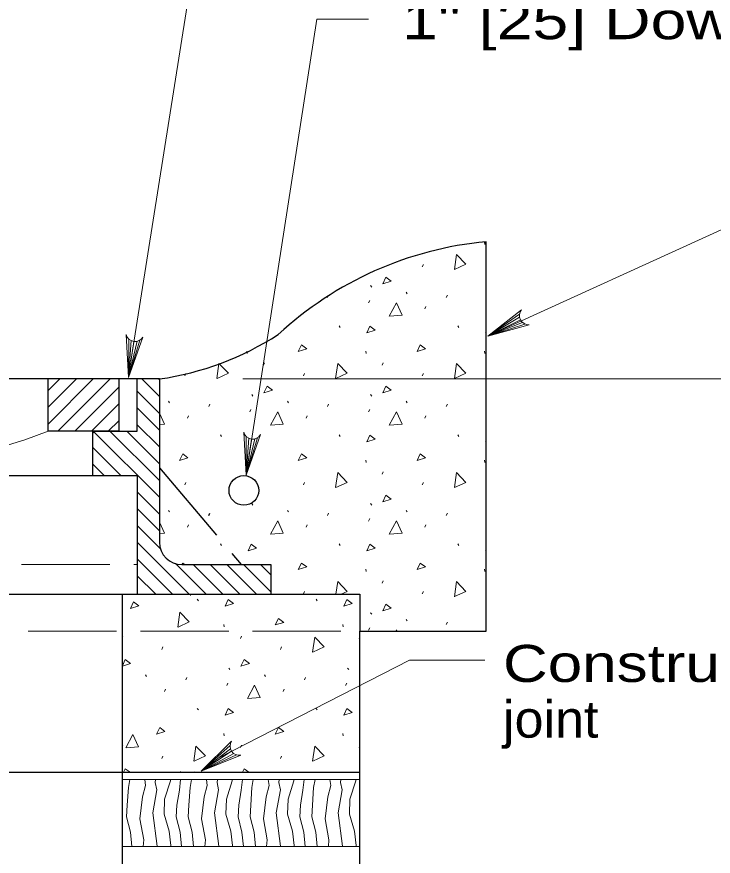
# Model space of a CAD drawing. Extents: x 1083.1 to 1117.1, y 719.4 to 763.4.
# Drawn here: x 1108.838 to 1111.769, y 732.781 to 736.318 of the extents above; entities that cross this region are included whole.
import ezdxf

# ---------------------------------------------------------------- set-up
doc = ezdxf.new("R2010")
doc.units = 0
doc.header["$LTSCALE"] = 0.062
doc.linetypes.add('LONG_DASHED', pattern=[7.5, 6, -1.5])
doc.layers.add('1', color=7, linetype='Continuous', lineweight=13)

msp = doc.modelspace()

# ---------------------------------------------------------------- linework, layer by layer
at = {"layer": '1'}
for p, q in [((1110.82092, 734.97183), (1112.03292, 735.52567)), ((1110.54475, 735.26408), (1110.54925, 735.27408)), ((1110.32733, 735.18533), (1110.33183, 735.17867)), ((1110.14583, 735.13533), (1110.1475, 735.139)), ((1110.47692, 735.15708), (1110.48133, 735.15042)), ((1110.64583, 735.13533), (1110.65025, 735.14533)), ((1110.319, 735.11217), (1110.32342, 735.12217)), ((1110.55592, 735.08675), (1110.56033, 735.09658)), ((1110.95367, 735.0645), (1110.82092, 734.97183)), ((1110.95392, 735.05208), (1110.82092, 734.97183)), ((1110.9575, 735.04125), (1110.82092, 734.97183)), ((1110.96658, 735.02975), (1110.82092, 734.97183)), ((1110.97675, 735.02325), (1110.82092, 734.97183)), ((1110.19467, 735.01567), (1110.19908, 735.009)), ((1110.69458, 735.01567), (1110.69908, 735.009)), ((1110.81108, 734.98683), (1110.81358, 734.992)), ((1110.81358, 734.98758), (1110.81108, 734.98683)), ((1109.30917, 734.96033), (1109.30842, 734.7985)), ((1109.35617, 734.9555), (1109.30842, 734.7985)), ((1109.31933, 734.95342), (1109.30842, 734.7985)), ((1109.345, 734.95092), (1109.30842, 734.7985)), ((1109.33033, 734.95017), (1109.30842, 734.7985)), ((1109.80683, 734.90917), (1109.808, 734.89917)), ((1110.30683, 734.90917), (1110.308, 734.89917)), ((1110.80675, 734.90917), (1110.80792, 734.89917)), ((1109.87608, 734.85025), (1109.8805, 734.86025)), ((1110.37608, 734.85025), (1110.3805, 734.86025)), ((1109.54475, 734.80475), (1109.54917, 734.8145)), ((1110.04475, 734.80475), (1110.04925, 734.81475)), ((1110.54475, 734.80475), (1110.54925, 734.81475)), ((1108.96983, 734.74358), (1109.01858, 734.79233)), ((1108.96983, 734.67283), (1109.08933, 734.79233)), ((1108.96983, 734.60217), (1109.16, 734.79233)), ((1109.01092, 734.5725), (1109.23075, 734.79233)), ((1109.43867, 734.7175), (1109.36392, 734.79225)), ((1109.43867, 734.78825), (1109.43467, 734.79217)), ((1109.43867, 734.78825), (1109.43467, 734.79217)), ((1112.95483, 734.79242), (1109.78875, 734.79242)), ((1109.08167, 734.5725), (1109.26675, 734.75758)), ((1109.43867, 734.64675), (1109.34492, 734.7405)), ((1109.82733, 734.726), (1109.83183, 734.71933)), ((1110.32733, 734.726), (1110.33183, 734.71933)), ((1109.15233, 734.5725), (1109.26675, 734.68692)), ((1109.43867, 734.57608), (1109.34492, 734.66983)), ((1109.47692, 734.69775), (1109.48133, 734.69108)), ((1109.64583, 734.676), (1109.65025, 734.686)), ((1109.97692, 734.69775), (1109.98133, 734.69108)), ((1110.14583, 734.676), (1110.15025, 734.686)), ((1110.47692, 734.69775), (1110.48133, 734.69108)), ((1110.64583, 734.676), (1110.65025, 734.686)), ((1109.55592, 734.62733), (1109.56033, 734.63725)), ((1109.819, 734.65283), (1109.82342, 734.66283)), ((1110.05592, 734.62733), (1110.06033, 734.63725)), ((1110.319, 734.65283), (1110.32342, 734.66283)), ((1110.55592, 734.62733), (1110.56033, 734.63725)), ((1109.22308, 734.5725), (1109.26675, 734.61617)), ((1109.43867, 734.50542), (1109.34492, 734.59908)), ((1109.15742, 734.56292), (1109.167, 734.5725)), ((1109.43867, 734.29333), (1109.15942, 734.5725)), ((1109.43867, 734.364), (1109.23008, 734.5725)), ((1109.43867, 734.43475), (1109.30083, 734.5725)), ((1109.69467, 734.55625), (1109.69908, 734.54958)), ((1109.804, 734.54908), (1109.80325, 734.38725)), ((1109.851, 734.54425), (1109.80325, 734.38725)), ((1109.81417, 734.54217), (1109.80325, 734.38725)), ((1109.83983, 734.53967), (1109.80325, 734.38725)), ((1109.82517, 734.53892), (1109.80325, 734.38725)), ((1110.19467, 734.55625), (1110.19908, 734.54958)), ((1110.69458, 734.55625), (1110.69908, 734.54958)), ((1110.81108, 734.5275), (1110.81358, 734.53267)), ((1110.81358, 734.52825), (1110.81108, 734.5275)), ((1109.27617, 734.38508), (1109.15742, 734.50383)), ((1109.2055, 734.38508), (1109.15742, 734.43317)), ((1110.30683, 734.44983), (1110.308, 734.43983)), ((1110.80675, 734.44983), (1110.80792, 734.43983)), ((1109.34492, 733.88517), (1109.34492, 734.38508)), ((1110.37608, 734.39092), (1110.3805, 734.40092)), ((1109.54475, 734.34542), (1109.54925, 734.35542)), ((1110.04475, 734.34542), (1110.04925, 734.35542)), ((1110.54475, 734.34542), (1110.54925, 734.35542)), ((1109.43867, 734.22258), (1109.34492, 734.31633)), ((1109.43867, 734.15192), (1109.34492, 734.24567)), ((1109.82733, 734.26667), (1109.83183, 734.26)), ((1110.32733, 734.26667), (1110.33183, 734.26)), ((1109.47692, 734.23842), (1109.48133, 734.23175)), ((1109.97692, 734.23842), (1109.98133, 734.23175)), ((1110.14583, 734.21667), (1110.15025, 734.22667)), ((1110.47692, 734.23842), (1110.48133, 734.23175)), ((1110.64583, 734.21667), (1110.65025, 734.22667)), ((1109.44325, 734.07667), (1109.34492, 734.17492)), ((1109.55592, 734.168), (1109.56033, 734.178)), ((1110.05592, 734.168), (1110.06033, 734.178)), ((1110.319, 734.1935), (1110.32342, 734.2035)), ((1110.55592, 734.168), (1110.56033, 734.178)), ((1109.56408, 733.88517), (1109.34492, 734.10425)), ((1109.69467, 734.09692), (1109.69908, 734.09025)), ((1110.19467, 734.09692), (1110.19908, 734.09025)), ((1110.69458, 734.09692), (1110.69908, 734.09025)), ((1110.81108, 734.06808), (1110.81358, 734.07325)), ((1110.81358, 734.06883), (1110.81108, 734.06808)), ((1109.49333, 733.88517), (1109.34492, 734.0335)), ((1109.63475, 733.88517), (1109.5055, 734.01433)), ((1109.7055, 733.88517), (1109.5805, 734.01008)), ((1109.77617, 733.88517), (1109.65117, 734.01008)), ((1109.84692, 733.88517), (1109.72192, 734.01008)), ((1109.90742, 733.89533), (1109.79258, 734.01008)), ((1109.90742, 733.96608), (1109.86333, 734.01008)), ((1109.42267, 733.88517), (1109.34492, 733.96292)), ((1110.30683, 733.99042), (1110.308, 733.9805)), ((1110.80675, 733.99042), (1110.80792, 733.9805)), ((1110.37608, 733.93158), (1110.3805, 733.94158)), ((1110.04475, 733.88608), (1110.04925, 733.89608)), ((1110.54475, 733.88608), (1110.54925, 733.89608)), ((1109.28242, 733.88517), (1110.28242, 733.88517)), ((1109.56858, 733.88008), (1109.56783, 733.88517)), ((1109.59783, 733.86367), (1109.60225, 733.857)), ((1110.09783, 733.86367), (1110.10225, 733.857)), ((1110.32733, 733.80733), (1110.33183, 733.80067)), ((1110.32733, 733.80733), (1110.32758, 733.807)), ((1109.71, 733.75717), (1109.71117, 733.74717)), ((1110.21, 733.75717), (1110.21117, 733.74717)), ((1110.47692, 733.77908), (1110.48133, 733.77242)), ((1110.64583, 733.75733), (1110.65025, 733.76733)), ((1110.319, 733.73417), (1110.32342, 733.74417)), ((1109.28242, 733.70542), (1109.28367, 733.70825)), ((1109.77925, 733.69825), (1109.78367, 733.70825)), ((1110.27925, 733.69825), (1110.28242, 733.70542)), ((1109.44792, 733.65275), (1109.45242, 733.66275)), ((1109.94792, 733.65275), (1109.95242, 733.66275)), ((1109.7305, 733.574), (1109.735, 733.56733)), ((1110.2305, 733.574), (1110.235, 733.56733)), ((1110.28142, 733.58175), (1110.28242, 733.58383)), ((1110.28242, 733.58208), (1110.28142, 733.58175)), ((1109.38008, 733.54575), (1109.3845, 733.53908)), ((1109.88008, 733.54575), (1109.8845, 733.53908)), ((1109.549, 733.524), (1109.55342, 733.534)), ((1109.72217, 733.50083), (1109.72658, 733.51083)), ((1110.049, 733.524), (1110.05342, 733.534)), ((1110.22217, 733.50083), (1110.22658, 733.51083)), ((1109.45908, 733.47533), (1109.4635, 733.48525)), ((1109.95908, 733.47533), (1109.9635, 733.48525)), ((1109.59783, 733.40433), (1109.60225, 733.39767)), ((1110.09783, 733.40433), (1110.10225, 733.39767)), ((1109.71, 733.29783), (1109.71117, 733.28783)), ((1110.21, 733.29783), (1110.21117, 733.28783)), ((1109.28242, 733.24608), (1109.28367, 733.24892)), ((1109.73533, 733.24667), (1109.61342, 733.14017)), ((1109.73683, 733.23442), (1109.61342, 733.14017)), ((1109.74167, 733.224), (1109.61342, 733.14017)), ((1109.77925, 733.23892), (1109.78367, 733.24892)), ((1110.27925, 733.23892), (1110.28242, 733.24608)), ((1109.44792, 733.19342), (1109.45242, 733.20342)), ((1109.75192, 733.2135), (1109.61342, 733.14017)), ((1109.76275, 733.20817), (1109.61342, 733.14017)), ((1109.94792, 733.19342), (1109.95242, 733.20342)), ((1109.52592, 733.13525), (1109.5265, 733.13825)), ((1109.28008, 733.104), (1109.28242, 733.104)), ((1109.28242, 733.104), (1110.28242, 733.104)), ((1109.28008, 732.82283), (1109.28242, 732.82283)), ((1109.28242, 732.82283), (1110.28242, 732.82283))]:
    msp.add_line(p, q, dxfattribs=at)
at = {"layer": '1', "lineweight": 25}
for p, q in [((1110.80675, 735.3685), (1110.80792, 735.3585)), ((1109.43867, 734.79217), (1106.97008, 734.79308)), ((1109.26675, 734.79225), (1109.26675, 734.5725)), ((1109.43867, 734.79217), (1109.43867, 734.10383)), ((1106.97008, 734.38508), (1109.34492, 734.38508)), ((1109.34492, 734.38508), (1109.34492, 733.88517)), ((1109.64583, 734.21667), (1109.65025, 734.22667)), ((1107.03258, 733.88517), (1110.28242, 733.88517)), ((1109.28242, 729.63575), (1109.28242, 733.88517)), ((1110.28242, 733.88517), (1110.28242, 733.72892)), ((1106.59033, 733.13525), (1108.96575, 733.13525)), ((1108.96575, 733.13525), (1110.28242, 733.13525))]:
    msp.add_line(p, q, dxfattribs=at)
at = {"layer": '1', "linetype": 'LONG_DASHED', "lineweight": 25}
msp.add_line((1109.43867, 734.41817), (1109.78242, 734.01008), dxfattribs=at)
at = {"layer": '1', "linetype": 'LONG_DASHED'}
for p, q in [((1106.97008, 734.01008), (1109.34492, 734.01008)), ((1107.94217, 733.72892), (1110.28242, 733.72892))]:
    msp.add_line(p, q, dxfattribs=at)
at = {"layer": '1'}
for points in [[(1109.31842, 734.86733), (1109.73517, 737.50142), (1109.95267, 737.50142)], [(1109.80317, 734.38775), (1110.101, 736.30775), (1110.3185, 736.30775)], [(1110.67983, 735.25258), (1110.68867, 735.31608), (1110.72833, 735.275), (1110.68083, 735.253)], [(1110.406, 735.05675), (1110.436, 735.11325), (1110.45933, 735.06117), (1110.40717, 735.05675)], [(1110.99483, 735.0205), (1110.82092, 734.97183), (1110.96275, 735.08367)], [(1109.36875, 734.96867), (1109.30842, 734.7985), (1109.29867, 734.97883)], [(1109.67983, 734.79325), (1109.68867, 734.85675), (1109.72842, 734.81567), (1109.68083, 734.79367)], [(1110.17983, 734.79325), (1110.18867, 734.85675), (1110.22842, 734.81567), (1110.18083, 734.79367)], [(1110.67983, 734.79325), (1110.68867, 734.85675), (1110.72833, 734.81567), (1110.68083, 734.79367)], [(1109.43867, 734.64792), (1109.45933, 734.60175), (1109.43867, 734.6)], [(1109.906, 734.59733), (1109.936, 734.65392), (1109.95933, 734.60175), (1109.90717, 734.59733)], [(1110.406, 734.59733), (1110.436, 734.65392), (1110.45933, 734.60175), (1110.40717, 734.59733)], [(1109.86358, 734.55742), (1109.80325, 734.38725), (1109.7935, 734.56758)], [(1110.17983, 734.334), (1110.18867, 734.39742), (1110.22842, 734.35633), (1110.18083, 734.33433)], [(1110.67983, 734.334), (1110.68867, 734.39742), (1110.72833, 734.35633), (1110.68083, 734.33433)], [(1109.43867, 734.18858), (1109.45933, 734.14242), (1109.43867, 734.14067)], [(1109.906, 734.138), (1109.936, 734.19458), (1109.95933, 734.14242), (1109.90717, 734.138)], [(1110.406, 734.138), (1110.436, 734.19458), (1110.45933, 734.14242), (1110.40717, 734.138)], [(1109.53308, 734.01008), (1109.53617, 734.0165), (1109.54467, 734.01008)], [(1110.18133, 733.88517), (1110.18867, 733.93808), (1110.22842, 733.897), (1110.20283, 733.88517)], [(1110.67983, 733.87467), (1110.68867, 733.93808), (1110.72833, 733.897), (1110.68083, 733.875)], [(1109.51558, 733.74625), (1109.52442, 733.80975), (1109.56417, 733.76867), (1109.51658, 733.74667)], [(1110.43267, 733.72892), (1110.436, 733.73525), (1110.43883, 733.72892)], [(1110.083, 733.64125), (1110.09183, 733.70475), (1110.13158, 733.66367), (1110.084, 733.64167)], [(1109.28242, 733.58383), (1109.29475, 733.6095), (1109.317, 733.59283), (1109.28242, 733.58208)], [(1109.68575, 733.19417), (1110.4905, 733.60683), (1110.8075, 733.60683)], [(1109.80917, 733.44533), (1109.83917, 733.50192), (1109.8625, 733.44983), (1109.81033, 733.44533)], [(1109.29667, 733.23783), (1109.32667, 733.29442), (1109.35, 733.24225), (1109.29783, 733.23783)], [(1109.781, 733.20742), (1109.61342, 733.14017), (1109.74225, 733.26667)], [(1109.583, 733.182), (1109.59183, 733.24542), (1109.63158, 733.20433), (1109.584, 733.18233)], [(1110.083, 733.182), (1110.09183, 733.24542), (1110.13158, 733.20433), (1110.084, 733.18233)], [(1109.28758, 733.13525), (1109.29475, 733.15017), (1109.31467, 733.13525)], [(1109.78758, 733.13525), (1109.79475, 733.15017), (1109.81467, 733.13525)], [(1109.60817, 733.13525), (1109.58792, 733.13642), (1109.58683, 733.13525)], [(1109.32225, 732.82283), (1109.3165, 732.88217), (1109.29992, 732.94658), (1109.30275, 732.99633), (1109.30742, 733.07108), (1109.31333, 733.104)], [(1109.36933, 732.82283), (1109.372, 732.85067), (1109.35608, 732.93858), (1109.36692, 733.03183), (1109.37983, 733.07992), (1109.37617, 733.104)], [(1109.42842, 732.82283), (1109.4285, 732.82317), (1109.41008, 732.96442), (1109.42733, 733.06058), (1109.42083, 733.09208), (1109.42225, 733.104)], [(1109.48467, 733.104), (1109.48433, 733.09833), (1109.46008, 733.02233), (1109.45775, 732.95858), (1109.47875, 732.8875), (1109.48592, 732.82717), (1109.48583, 732.82283)], [(1109.53158, 732.82283), (1109.52583, 732.88217), (1109.50925, 732.94658), (1109.512, 732.99633), (1109.52217, 733.05992), (1109.52742, 733.104)], [(1109.58225, 732.82283), (1109.5765, 732.88217), (1109.55992, 732.94658), (1109.56275, 732.99633), (1109.56742, 733.07108), (1109.57333, 733.104)], [(1109.62933, 732.82283), (1109.632, 732.85067), (1109.61608, 732.93858), (1109.62692, 733.03183), (1109.63983, 733.07992), (1109.63617, 733.104)], [(1109.68842, 732.82283), (1109.6885, 732.82317), (1109.67008, 732.96442), (1109.68733, 733.06058), (1109.68083, 733.09208), (1109.68225, 733.104)], [(1109.74467, 733.104), (1109.74433, 733.09833), (1109.72008, 733.02233), (1109.71775, 732.95858), (1109.73875, 732.8875), (1109.74592, 732.82717), (1109.74583, 732.82283)], [(1109.79158, 732.82283), (1109.78583, 732.88217), (1109.76925, 732.94658), (1109.772, 732.99633), (1109.78217, 733.05992), (1109.78742, 733.104)], [(1109.84225, 732.82283), (1109.8365, 732.88217), (1109.81992, 732.94658), (1109.82275, 732.99633), (1109.82742, 733.07108), (1109.83333, 733.104)], [(1109.88933, 732.82283), (1109.892, 732.85067), (1109.87608, 732.93858), (1109.88692, 733.03183), (1109.89983, 733.07992), (1109.89617, 733.104)], [(1109.94842, 732.82283), (1109.9485, 732.82317), (1109.93008, 732.96442), (1109.94733, 733.06058), (1109.94083, 733.09208), (1109.94225, 733.104)], [(1110.00467, 733.104), (1110.00433, 733.09833), (1109.98008, 733.02233), (1109.97775, 732.95858), (1109.99875, 732.8875), (1110.00592, 732.82717), (1110.00583, 732.82283)], [(1110.05158, 732.82283), (1110.04583, 732.88217), (1110.02925, 732.94658), (1110.032, 732.99633), (1110.04217, 733.05992), (1110.04742, 733.104)], [(1110.10225, 732.82283), (1110.0965, 732.88217), (1110.07992, 732.94658), (1110.08275, 732.99633), (1110.08742, 733.07108), (1110.09333, 733.104)], [(1110.14933, 732.82283), (1110.152, 732.85067), (1110.13608, 732.93858), (1110.14692, 733.03183), (1110.15983, 733.07992), (1110.15617, 733.104)], [(1110.20842, 732.82283), (1110.2085, 732.82317), (1110.19008, 732.96442), (1110.20733, 733.06058), (1110.20083, 733.09208), (1110.20225, 733.104)], [(1110.26467, 733.104), (1110.26433, 733.09833), (1110.24008, 733.02233), (1110.23775, 732.95858), (1110.25875, 732.8875), (1110.26592, 732.82717), (1110.26583, 732.82283)]]:
    msp.add_lwpolyline(points, dxfattribs=at)
at = {"layer": '1', "lineweight": 25}
for points in [[(1110.28242, 733.72892), (1110.81358, 733.72892), (1110.81358, 735.37017)], [(1109.26675, 734.5725), (1108.96983, 734.5725), (1108.96983, 734.79233)], [(1109.15742, 734.38508), (1109.15742, 734.5725), (1109.34492, 734.5725), (1109.34492, 734.79217)], [(1109.53242, 734.01008), (1109.90742, 734.01008), (1109.90742, 733.88517)], [(1110.28242, 732.20567), (1110.28242, 733.23258), (1110.28242, 733.72892)]]:
    msp.add_lwpolyline(points, dxfattribs=at)
at = {"layer": '1'}
for points in [[(1110.37825, 735.19308), (1110.39158, 735.22083), (1110.41383, 735.20417)], [(1110.31117, 734.98683), (1110.3245, 735.01458), (1110.34675, 734.99792)], [(1110.02283, 734.9075), (1110.03617, 734.93525), (1110.05833, 734.91858)], [(1110.52283, 734.9075), (1110.53617, 734.93525), (1110.55833, 734.91858)], [(1109.87825, 734.73375), (1109.89158, 734.7615), (1109.91383, 734.74483)], [(1110.37825, 734.73375), (1110.39158, 734.7615), (1110.41383, 734.74483)], [(1110.31117, 734.5275), (1110.3245, 734.55517), (1110.34675, 734.5385)], [(1109.52283, 734.44817), (1109.53617, 734.47592), (1109.55833, 734.45925)], [(1110.02283, 734.44817), (1110.03617, 734.47592), (1110.05833, 734.45925)], [(1110.52283, 734.44817), (1110.53617, 734.47592), (1110.55833, 734.45925)], [(1110.37825, 734.27442), (1110.39158, 734.30217), (1110.41383, 734.2855)], [(1109.81117, 734.06808), (1109.8245, 734.09583), (1109.84675, 734.07917)], [(1110.31117, 734.06808), (1110.3245, 734.09583), (1110.34675, 734.07917)], [(1110.02283, 733.98883), (1110.03617, 734.0165), (1110.05833, 733.99983)], [(1110.52283, 733.98883), (1110.53617, 734.0165), (1110.55833, 733.99983)], [(1109.71433, 733.83483), (1109.72767, 733.86258), (1109.74992, 733.84592)], [(1110.21433, 733.83483), (1110.22767, 733.86258), (1110.24992, 733.84592)], [(1109.31617, 733.8255), (1109.3295, 733.85325), (1109.35167, 733.83658)], [(1110.37825, 733.81508), (1110.39158, 733.84283), (1110.41383, 733.82617)], [(1109.926, 733.7555), (1109.93933, 733.78325), (1109.9615, 733.76658)], [(1109.78142, 733.58175), (1109.79475, 733.6095), (1109.817, 733.59283)], [(1109.71433, 733.3755), (1109.72767, 733.40325), (1109.74992, 733.38658)], [(1110.21433, 733.3755), (1110.22767, 733.40325), (1110.24992, 733.38658)], [(1109.426, 733.29617), (1109.43933, 733.32392), (1109.4615, 733.30725)], [(1109.926, 733.29617), (1109.93933, 733.32392), (1109.9615, 733.30725)]]:
    msp.add_lwpolyline(points, close=True, dxfattribs=at)
for centre, start, end in [((1110.99153, 735.05858), 139.0177, 274.84383), ((1109.33574, 734.98789), 193.88148, 329.70761), ((1109.83057, 734.57666), 193.88148, 329.70761), ((1109.77357, 733.24491), 145.27383, 281.09996)]:
    msp.add_arc(centre, 0.03822, start, end, dxfattribs=at)
at = {"layer": '1', "lineweight": 25}
for centre, major_axis, start_param, end_param in [((1110.95294, 733.88287), (-1.49396, 0), 4.8057808, 5.4586777), ((1109.26682, 736.01073), (1.23075, 0), 4.8524907, 5.2898286), ((1109.53243, 734.10386), (-0.09375, 0), 6.2831853, 7.8539816)]:
    msp.add_ellipse(centre, major_axis=major_axis, ratio=0.999895, start_param=start_param, end_param=end_param, dxfattribs=at)
at = {"layer": '1'}
msp.add_ellipse((1108.15749, 736.60617), major_axis=(-2.19009, 0), ratio=0.999895, start_param=1.1907817, end_param=1.9508109, dxfattribs=at)
at = {"layer": '1', "lineweight": 25}
msp.add_ellipse((1109.79377, 734.32257), major_axis=(0.0625, 0), ratio=0.999895, dxfattribs=at)

# ---------------------------------------------------------------- texts
at = {"layer": '1'}
for s, width, p in [('1" [25] Dowel', 1.3, (1110.45975, 736.22333)), ('Construction', 1.25, (1110.8845, 733.5155)), ('joint', 1.05, (1110.8845, 733.28083))]:
    msp.add_text(s, height=0.156, dxfattribs=dict(at, width=width)).set_placement(p)

doc.saveas('drawing.dxf')
